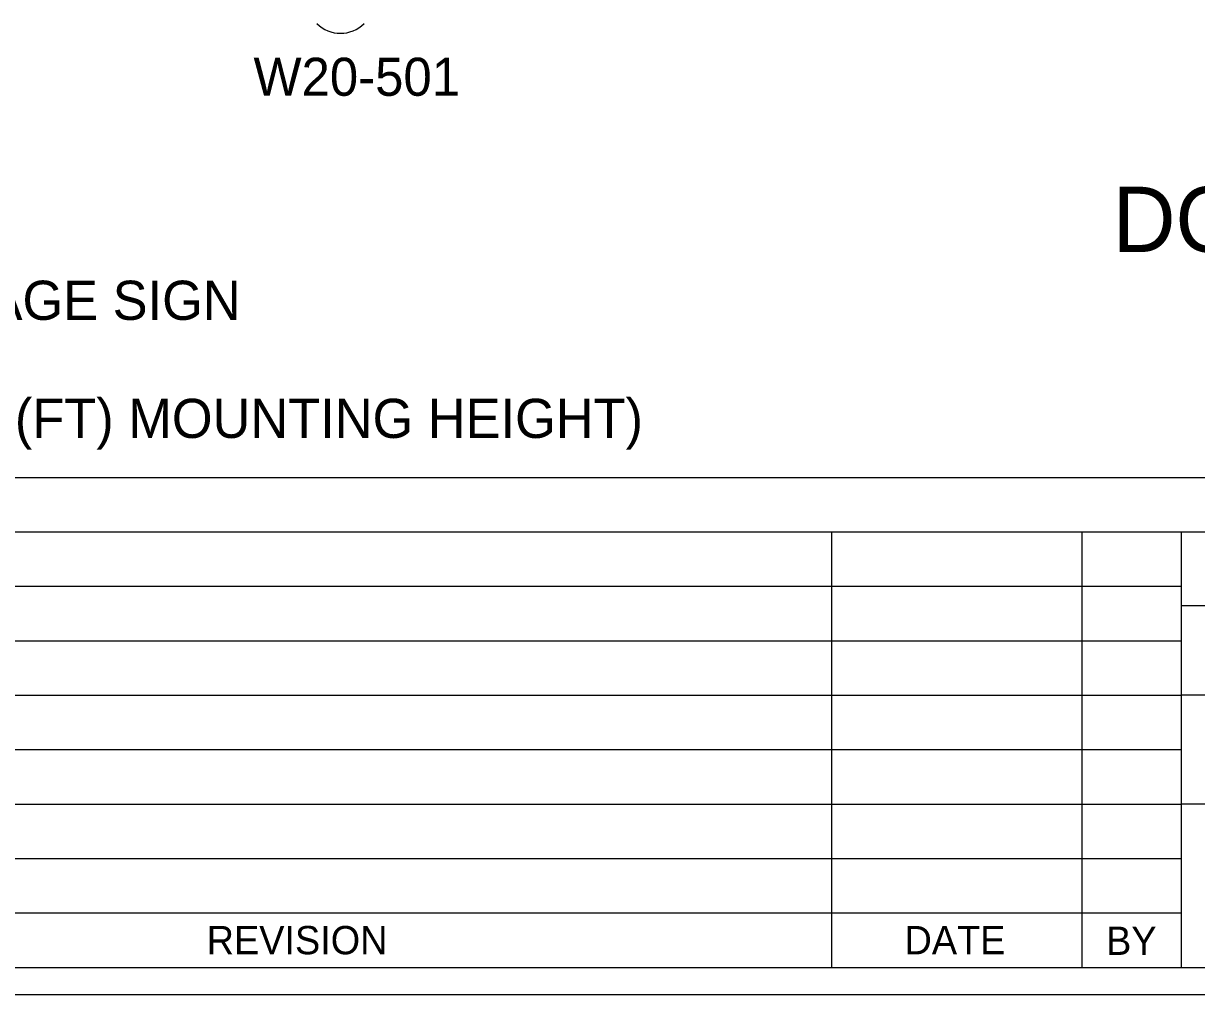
# Model space of a CAD drawing. Extents: x 99988 to 100172, y 99995 to 100047.
# Drawn here: x 100002.784 to 100005.48, y 99999.937 to 100002.169 of the extents above; entities that cross this region are included whole.
import ezdxf

# ---------------------------------------------------------------- set-up
doc = ezdxf.new("R2010")
doc.units = 0
for name, color, linetype in [('SH_DE_DetailBody1Text', 7, 'Continuous'), ('SH_DE_DetailHeading1Text', 7, 'Continuous'), ('SH_GI_PlotLimits', 7, 'Continuous'), ('SH_GI_SheetBorder', 7, 'Continuous'), ('SH_GI_SheetTextInCells', 7, 'Continuous'), ('TR_SN_WarningSigns', 7, 'Continuous')]:
    doc.layers.add(name, color=color, linetype=linetype)

msp = doc.modelspace()

# ---------------------------------------------------------------- linework, layer by layer
at = {"layer": 'SH_GI_PlotLimits'}
msp.add_lwpolyline([(99999.3125, 99999.9375), (100015.8125, 99999.9375), (100015.8125, 100010.4375), (99999.3125, 100010.4375)], close=True, dxfattribs=at)
at = {"layer": 'SH_GI_SheetBorder'}
for p, q in [((100000, 100001.1259), (100015.75, 100001.1259)), ((100000, 100001.0008), (100007.4566, 100001.0008)), ((100004.641, 100001.0008), (100004.641, 100000)), ((100005.2164, 100001.0008), (100005.2164, 100000)), ((100005.4451, 100001.0008), (100005.4451, 100000)), ((100002.1821, 100000.8757), (100005.4466, 100000.8757)), ((100006.0958, 100000.831), (100005.4466, 100000.831)), ((100002.1821, 100000.7506), (100005.4466, 100000.7506)), ((100000, 100000.6255), (100005.4466, 100000.6255)), ((100006.0958, 100000.6255), (100005.4466, 100000.6255)), ((100000, 100000.5004), (100005.4466, 100000.5004)), ((100000, 100000.3753), (100005.4466, 100000.3753)), ((100007.4566, 100000.3753), (100005.4466, 100000.3753)), ((100000, 100000.2502), (100005.4466, 100000.2502)), ((100000, 100000.1251), (100005.4466, 100000.1251)), ((100000, 100000), (100015.75, 100000))]:
    msp.add_line(p, q, dxfattribs=at)
at = {"layer": 'TR_SN_WarningSigns'}
msp.add_arc((100003.5124, 100002.2235), 0.0769, 225, 314.9996, dxfattribs=at)

# ---------------------------------------------------------------- texts
at = {"layer": 'SH_DE_DetailBody1Text'}
for s, p in [('PORTABLE CHANGEABLE MESSAGE SIGN', (100000.8284, 100001.488)), ("TEMPORARY SIGN LOCATION (5' (FT) MOUNTING HEIGHT)", (100000.8284, 100001.2166))]:
    msp.add_text(s, height=0.09, dxfattribs=at).set_placement(p)
at = {"layer": 'SH_DE_DetailHeading1Text'}
msp.add_text('DOUBLE-LANE CLOSURE FOR MULTI-LANE ROADWAYS', height=0.15, dxfattribs=at).set_placement((100005.2875, 100001.644))
at = {"layer": 'SH_GI_SheetTextInCells'}
for s, p in [('REVISION', (100003.2048, 100000.03)), ('DATE', (100004.8091, 100000.03)), ('BY', (100005.2725, 100000.0285))]:
    msp.add_text(s, height=0.06505, dxfattribs=at).set_placement(p)
at = {"layer": 'TR_SN_WarningSigns'}
msp.add_text('W20-501', height=0.0875, rotation=360, dxfattribs=at).set_placement((100003.3125, 100002.0029))

doc.saveas('drawing.dxf')
